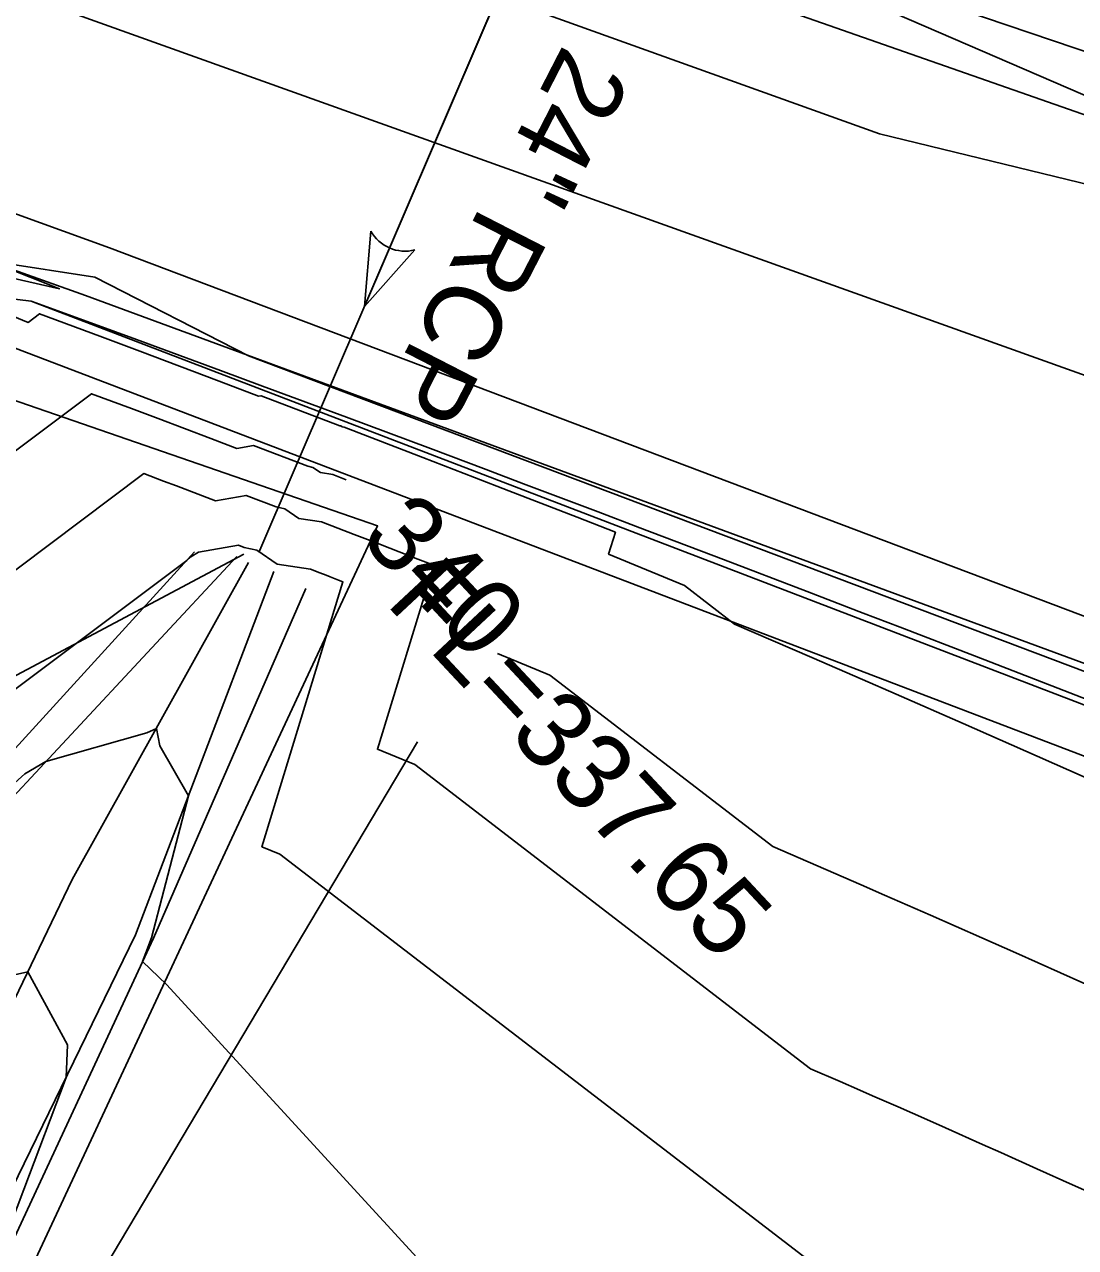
# Model space of a CAD drawing. Extents: x 487096 to 489566, y 221939 to 224454.
# Drawn here: x 488176.4 to 488220.2, y 223618.2 to 223669.2 of the extents above; entities that cross this region are included whole.
import ezdxf

# ---------------------------------------------------------------- set-up
doc = ezdxf.new("R2010")
doc.units = 0
for name, color, linetype in [('SV_BKLN_BKLN', 7, 'Continuous'), ('SV_BKLN_EARTH_TOP', 7, 'Continuous'), ('SV_DRAN_DRAN_TX', 7, 'Continuous'), ('SV_GDRL_GR', 7, 'Continuous'), ('SV_PIPE_CM_15', 7, 'Continuous'), ('SV_PIPE_FLOW', 7, 'Continuous'), ('SV_PIPE_RC_24', 7, 'Continuous'), ('SV_PIPE_RC_TX', 7, 'Continuous'), ('SV_ROAD_BITRD', 7, 'Continuous'), ('SV_ROWL_HWYLOC', 7, 'Continuous'), ('SV_SURF_INDEX_CONTOUR', 7, 'Continuous'), ('SV_SURF_INTER_CONTOUR', 7, 'Continuous'), ('SV_TRAF_PVMTL', 7, 'Continuous'), ('SV_TREE_TREEVEG', 7, 'Continuous'), ('SV_WATR_INWETF', 7, 'Continuous'), ('SV_WATR_STREAM', 7, 'Continuous')]:
    doc.layers.add(name, color=color, linetype=linetype)

msp = doc.modelspace()

# ---------------------------------------------------------------- linework, layer by layer
at = {"layer": 'SV_BKLN_BKLN'}
for points in [[(488221.825, 223640.605), (488219.505, 223641.507), (488216.023, 223642.856), (488212.926, 223644.051), (488211.378, 223644.647), (488209.054, 223645.54), (488205.566, 223646.874), (488202.076, 223648.203), (488200.33, 223648.866), (488197.225, 223650.04), (488195.672, 223650.625), (488193.341, 223651.5), (488189.843, 223652.809), (488186.342, 223654.11), (488184.591, 223654.758), (488181.086, 223656.049), (488179.332, 223656.692), (488176.701, 223657.653)], [(488185.761, 223646.754), (488178.404, 223633.53), (488164.187, 223603.969), (488123.062, 223563.855), (488120.727, 223543.932)]]:
    msp.add_lwpolyline(points, dxfattribs=at)
at = {"layer": 'SV_BKLN_EARTH_TOP'}
for points in [[(488183.509, 223647.201), (488173.424, 223636.168), (488156.231, 223626.396), (488147.92, 223603.515), (488119.192, 223564.038), (488115.257, 223542.544)], [(488188.143, 223645.663), (488181.789, 223631.086), (488167.758, 223600.89), (488125.642, 223563.239), (488125.985, 223541.73)]]:
    msp.add_lwpolyline(points, dxfattribs=at)
at = {"layer": 'SV_GDRL_GR'}
msp.add_lwpolyline([(488277.437, 223618.518), (488276.608, 223618.867), (488274.947, 223619.563), (488273.285, 223620.255), (488272.175, 223620.714), (488269.954, 223621.628), (488267.451, 223622.649), (488265.781, 223623.325), (488264.666, 223623.774), (488262.434, 223624.668), (488260.759, 223625.336), (488259.641, 223625.779), (488257.403, 223626.661), (488256.283, 223627.101), (488254.041, 223627.977), (488251.797, 223628.849), (488250.3, 223629.428), (488247.303, 223630.581), (488176.701, 223657.653), (488168.141, 223658.69), (488156.251, 223662.118)], dxfattribs=at)
at = {"layer": 'SV_PIPE_CM_15'}
msp.add_lwpolyline([(488383.932, 223595.701), (488200.041, 223675.131)], dxfattribs=at)
at = {"layer": 'SV_PIPE_FLOW'}
for p, q in [((488196.504, 223671.209), (488190.591, 223657.421)), ((488190.853, 223660.575), (488190.591, 223657.421)), ((488190.591, 223657.421), (488192.695, 223659.785))]:
    msp.add_line(p, q, dxfattribs=at)
msp.add_arc((488192.286, 223661.374), 1.639, 209.1863, 284.388, dxfattribs=at)
at = {"layer": 'SV_PIPE_RC_24'}
msp.add_lwpolyline([(488198.01, 223674.748), (488186.185, 223647.175)], dxfattribs=at)
at = {"layer": 'SV_ROAD_BITRD'}
for points in [[(488245.136, 223633.513), (488178.956, 223657.882), (488093.675, 223688.293)], [(488295.354, 223639.201), (488243.635, 223660.28), (488207.074, 223672.666)]]:
    msp.add_lwpolyline(points, dxfattribs=at)
at = {"layer": 'SV_ROWL_HWYLOC'}
msp.add_lwpolyline([(487750.085, 223817.31), (487833.808, 223784.325), (487880.612, 223763.007), (487930.047, 223747.42), (487951.568, 223737.026), (487996.658, 223715.694), (488020.227, 223704.757), (488056.94, 223694.065), (488093.652, 223683.373), (488127.207, 223671.393), (488156.251, 223662.118), (488168.141, 223658.69), (488264.6, 223621.902)], dxfattribs=at)
at = {"layer": 'SV_SURF_INDEX_CONTOUR'}
for points in [[(488117.486, 223626.708), (488120.369, 223627.417), (488123.659, 223629.603), (488156.248, 223655.74), (488160.008, 223656.441), (488169.289, 223653.797), (488175.711, 223651.163), (488179.216, 223653.792), (488180.883, 223653.169), (488181.988, 223652.754), (488184.185, 223651.924), (488185.276, 223651.509), (488185.969, 223651.629), (488188.234, 223650.765), (488188.434, 223650.719), (488188.755, 223650.5), (488189.275, 223650.421), (488189.833, 223650.207)], [(488196.138, 223642.96), (488198.313, 223642.058), (488207.611, 223634.912), (488209.833, 223633.951), (488211.299, 223633.313), (488212.27, 223632.889), (488214.196, 223632.044), (488216.337, 223631.1), (488217.749, 223630.474), (488220.538, 223629.233), (488221.914, 223628.618), (488224.632, 223627.4), (488227.305, 223626.199), (488229.064, 223625.407), (488232.529, 223623.847), (488250.321, 223614.684)]]:
    msp.add_lwpolyline(points, dxfattribs=at)
at = {"layer": 'SV_SURF_INTER_CONTOUR'}
for points in [[(488221.968, 223716.637), (488212.328, 223713.464), (488186.674, 223705.985), (488181.543, 223706.149), (488180.73, 223705.164), (488175.113, 223703.461), (488172.875, 223703.639), (488159.961, 223704.006), (488158.359, 223696.898), (488158.296, 223691.66), (488159.245, 223691.37), (488180.424, 223681.304), (488180.548, 223680.638), (488182.512, 223678.741), (488182.683, 223675.18), (488212.069, 223664.629), (488242.333, 223657.264)], [(488089.248, 223668.379), (488120.943, 223645.878), (488145.515, 223665.547), (488177.872, 223658.165), (488175.429, 223659.14), (488175.371, 223659.267), (488179.343, 223658.655), (488185.76, 223655.377), (488230.924, 223638.312)], [(488220.684, 223637.768), (488218.642, 223638.672), (488215.547, 223640.038), (488212.762, 223641.259), (488211.358, 223641.872), (488209.238, 223642.795), (488206.026, 223644.184), (488203.935, 223645.791), (488200.772, 223647.103), (488201.052, 223648.016), (488199.463, 223648.638), (488196.617, 223649.746), (488195.183, 223650.303), (488193.019, 223651.138), (488189.745, 223652.396), (488189.655, 223652.409), (488189.6, 223652.447), (488189.565, 223652.455), (488186.282, 223653.707), (488186.169, 223653.688), (488184.527, 223654.312), (488181.219, 223655.563), (488179.554, 223656.188), (488177.045, 223657.125), (488176.565, 223656.765), (488173.435, 223658.049)], [(488174.856, 223645.561), (488181.387, 223650.459), (488182.211, 223650.151), (488182.758, 223649.946), (488183.843, 223649.536), (488184.383, 223649.33), (488185.655, 223649.551), (488186.903, 223649.075), (488187.268, 223648.99), (488187.854, 223648.59), (488188.805, 223648.446), (488190.159, 223647.927), (488191.054, 223647.581), (488191.646, 223647.351), (488192.823, 223646.893), (488193.48, 223646.636), (488191.134, 223638.97), (488192.691, 223638.325), (488209.195, 223625.641), (488210.427, 223625.108), (488211.24, 223624.754), (488211.778, 223624.519), (488212.846, 223624.051), (488214.033, 223623.527), (488214.815, 223623.18), (488216.361, 223622.493), (488217.124, 223622.152), (488218.63, 223621.477), (488220.112, 223620.811), (488221.087, 223620.372)], [(488210.78, 223616.369), (488187.069, 223634.591), (488186.315, 223634.904), (488189.694, 223645.946), (488189.503, 223646.02), (488189.161, 223646.153), (488188.989, 223646.22), (488188.729, 223646.321), (488188.336, 223646.472), (488186.954, 223646.68), (488186.103, 223647.262), (488185.572, 223647.385), (488185.342, 223647.473), (488183.67, 223647.183), (488183.352, 223646.996), (488183.182, 223646.843), (488174.002, 223639.959), (488172.378, 223640.625), (488170.032, 223641.294), (488156.238, 223638.723), (488142.548, 223627.743), (488129.776, 223619.256), (488104.228, 223612.979)], [(488205.028, 223604.4), (488182.342, 223629.16), (488181.342, 223630.122), (488181.479, 223630.484), (488181.712, 223631.101), (488183.252, 223637.018), (488182.054, 223639.108), (488181.913, 223639.837), (488181.523, 223639.649), (488177.305, 223638.459), (488176.427, 223637.942), (488174.084, 223635.841), (488168.948, 223633.525), (488166.226, 223632.077), (488156.233, 223630.215), (488151.993, 223626.813), (488134.479, 223615.176)], [(488139.182, 223611.096), (488154.33, 223621.161), (488156.02, 223625.039), (488156.193, 223625.366), (488156.226, 223625.34), (488156.8, 223625.269), (488176.552, 223629.68), (488178.213, 223626.641), (488178.153, 223625.284), (488176.391, 223620.61), (488173.993, 223614.307)]]:
    msp.add_lwpolyline(points, dxfattribs=at)
at = {"layer": 'SV_TRAF_PVMTL'}
for points in [[(488277.085, 223622.239), (488274.904, 223623.195), (488273.813, 223623.67), (488272.174, 223624.379), (488270.534, 223625.084), (488269.713, 223625.435), (488268.07, 223626.133), (488267.247, 223626.48), (488266.012, 223626.999), (488264.547, 223627.61), (488263.814, 223627.914), (488262.713, 223628.369), (488261.059, 223629.046), (488259.404, 223629.718), (488258.575, 223630.052), (488256.915, 223630.715), (488256.084, 223631.045), (488254.836, 223631.537), (488253.169, 223632.188), (488252.335, 223632.511), (488251.082, 223632.993), (488249.199, 223633.709), (488179.956, 223659.88), (488023.172, 223716.696)], [(488242.485, 223657.774), (488197.684, 223673.452), (488156.594, 223687.777), (488086.228, 223713.025)], [(488239.515, 223647.795), (488153.716, 223678.517), (488083.451, 223703.825)]]:
    msp.add_lwpolyline(points, dxfattribs=at)
at = {"layer": 'SV_TREE_TREEVEG'}
msp.add_lwpolyline([(488167.812, 223598.305), (488191.141, 223648.279), (488087.406, 223684.159), (488015.832, 223708.569), (487929.946, 223745.803), (487829.66, 223784.606), (487827.212, 223771.149)], dxfattribs=at)
at = {"layer": 'SV_WATR_INWETF'}
for points in [[(488185.568, 223647.102), (488153.931, 223630.268), (488131.714, 223600.452), (488120.409, 223568.494)], [(488130.113, 223504.973), (488166.152, 223594.481), (488192.809, 223639.274)]]:
    msp.add_lwpolyline(points, dxfattribs=at)
at = {"layer": 'SV_WATR_STREAM'}
for points in [[(488185.272, 223647.004), (488174.617, 223635.576), (488156.488, 223626.168), (488149.174, 223603.064), (488120.184, 223563.998), (488117.563, 223543.453)], [(488186.809, 223646.373), (488181.05, 223631.228), (488166.854, 223602.105), (488124.857, 223563.778), (488125.404, 223542.898)]]:
    msp.add_lwpolyline(points, dxfattribs=at)

# ---------------------------------------------------------------- texts
at = {"layer": 'SV_DRAN_DRAN_TX'}
msp.add_text('FL=337.65', height=3.2, rotation=313.0386, dxfattribs=at).set_placement((488191.432, 223645.047))
at = {"layer": 'SV_PIPE_RC_TX'}
msp.add_text("24'' RCP", height=3.2, rotation=242.7922, dxfattribs=at).set_placement((488198.911, 223668.422))
at = {"layer": 'SV_SURF_INDEX_CONTOUR'}
msp.add_text('340', height=3.2, rotation=313.0259, dxfattribs=at).set_placement((488190.339, 223647.74))

doc.saveas('drawing.dxf')
